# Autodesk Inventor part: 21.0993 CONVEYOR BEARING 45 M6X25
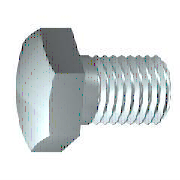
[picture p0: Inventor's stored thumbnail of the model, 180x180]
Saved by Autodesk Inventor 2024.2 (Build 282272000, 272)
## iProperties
Created: 2006-02
Part Number: 21.0993 CONVEYOR BEARING 45 M6X25
Material: Steel, Mild
Description: Hex-Head Bolt
Document SubType Name: Modeling
Standard: DIN 931-1
Designer: Andy Moles
Standards Organization: DIN
Language: en-US
Size Designation: M6 x 30
Categories: <MemberInstance><Categories><Category DisplayName="Fasteners" InternalName="e4da775c-781d-43d5-af7c-5136215cf5a6" Mnemonic="FSTN"><Category DisplayName="Bolts"
Density: 7.85 g/cm^3
Mass: 8.138 g
Surface Area: 7.68348 cm^2
Volume: 1.03669 cm^3
Appearance: Zinc
IsCustomPart: 1
Author: Andy Moles
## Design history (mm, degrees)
body "Solid1"
workplane "Work Plane1"
revolve "Body" stored, may be unused: angle "d12" = 90 deg
sketch "Sketch2"
  geometry: L1 (0, 5.774)-(5, 2.887); L2 (5, 2.887)-(5, -2.887); L3 (5, -2.887)-(0, -5.774); L4 (0, -5.774)-(-5, -2.887); L5 (-5, -2.887)-(-5, 2.887); L6 (-5, 2.887)-(0, 5.774); 2 further points
  constraints: 12 end point, 1 coincident, 1 vertical, 11 other
  dimensions: "d11" = 10 distance between parallel lines of L5 L2 (= SW)
extrude "Head" join sketch "Sketch2" distance "d3" = 3.5 (= KOH - SD); taper "d4" = 0 deg
revolve "Chamfer1" stored, may be unused: angle "d21" = 90 deg
feature "Thread" dims "d15" = 24 (= GEL), "d16" = 0
chamfer "Chamfer2" distance "d6" = 0.61345 (= -0.5 x SPD + 0.5 x GD); stored, may be unused: second distance "d7" = 0.61355 (computed from GUL), angle "d55" = 45 deg
sketch "Sketch1"
  geometry: L1 (0, 4.45)-(0, 3); L2 (1, 3)-(25, 3); L3 (25, 3)-(25, 0); L4 (25, 0)-(-0.5, 0); L5 (-3.05, 0)-(32.65, 0) reference; L6 (-0.5, 0)-(-0.5, 4.45); L7 (-0.5, 4.45)-(0, 4.45); L8 (1, 3)-(0.386, 3); L9 (0.386, 3)-(0, 3); L10 (0, -0.445)-(0, 5.785) reference
  constraints: 16 end point, 2 collinear, 2 perpendicular, 1 parallel
  dimensions: "d0" = 25 distance between parallel lines of L3 L1 (= NLG); "d1" = 24 distance from line of L2.start L3 (= GEL); "d2" = 6 diameter of L2 L4 (= GD); "d9" = 0.5001 distance between parallel lines of L6 L1 (computed from SD); "d10" = 8.9 diameter of L7 L4 (= SD2); "d13" = 0.61355 distance of L2.start L8.end (computed from GAL); "d14" = 6 diameter of L9 L4 (= BDM)
sketch "Sketch4"
  geometry: L1 (-4, 5)-(-4, 5.774); L2 (-4, 5.774)-(-3.554, 5.774); L3 (-3.554, 5.774)-(-4, 5); L4 (-4.35, 0)-(0.55, 0) reference; L5 (-0.5, 5.774)-(-4, 5.774) reference; L6 (-4, 2.887)-(-4, 5.774) reference
  constraints: 6 end point, 2 collinear, 1 perpendicular, 1 vertical
  dimensions: "d5" = 30 deg angle of L3 L1 (= ANG1); "d19" = 10 diameter of L1.start L4 (= SW0)
other parameters: "NLG" = 25 [user parameter; used in 1 equation term], "GD" = 6 (= NND) [user parameter; used in 2 equation terms], "BDM" = 6 (= NND) [user parameter; used in 1 equation term], "KOH" = 4 [user parameter; used in 1 equation term], "GEL" = 24 [user parameter; used in 2 equation terms], "SW" = 10 [user parameter; used in 3 equation terms], "SW0" = 10 (= SW) [user parameter; used in 1 equation term], "SPD" = 4.7731 (= NND - 1.2269 x PTC) [user parameter; used in 1 equation term], "SD2" = 8.9 [user parameter; used in 1 equation term], "SD" = 0.5 [user parameter; used in 2 equation terms], "ANG1" = 30 deg [user parameter; used in 1 equation term], "GAL" = 0.61345 (= 0.61345 x PTC) [user parameter; used in 1 equation term], "GUL" = 0.61345 (= 0.61345 x PTC) [user parameter; used in 1 equation term], "d8" = 0, "RR" = 0.25 [user parameter], "d57" = 0, "d58" = 0, "GD1" = 4.7731 (= THREADDIA - 1.2269 x PTC) [user parameter], "THREADDIA" = 6 [user parameter; used in 1 equation term], "TOA" = 30 deg [user parameter], "PTC" = 1 [user parameter; used in 5 equation terms], "NND" = 6 [user parameter; used in 3 equation terms], "E0" = 11.55 (= 1.155 x SW) [user parameter]
